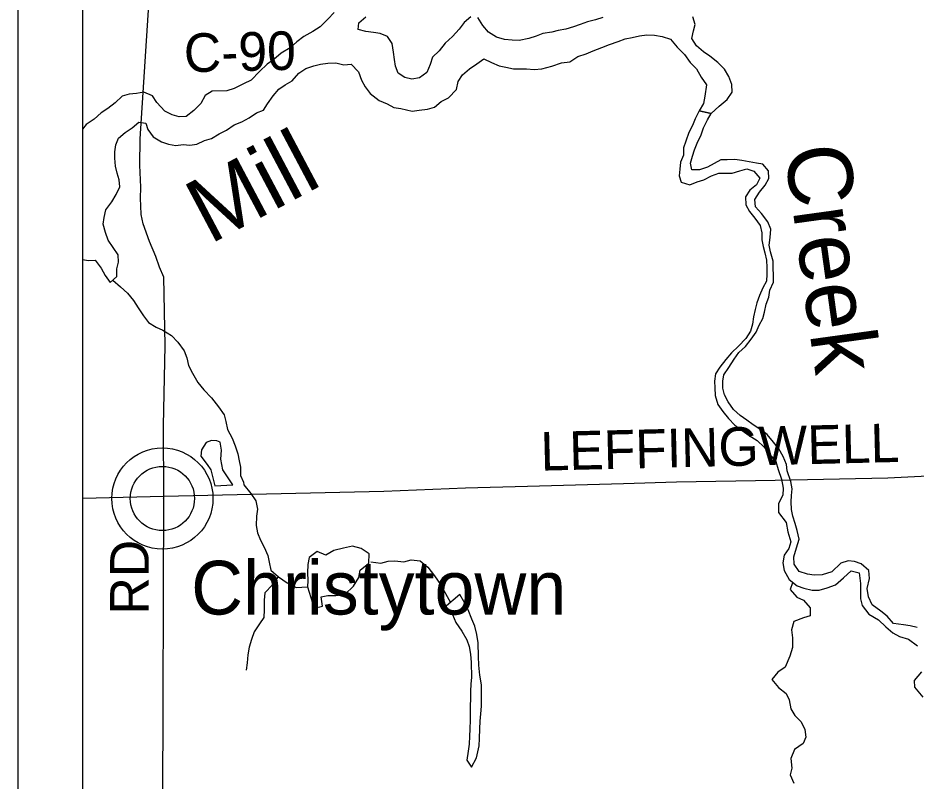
# Model space of a CAD drawing. Extents: x 0 to 34, y 0 to 22.
# Drawn here: x 2.895 to 4.215, y 15.405 to 16.527 of the extents above; entities that cross this region are included whole.
import ezdxf

# ---------------------------------------------------------------- set-up
doc = ezdxf.new("R2010")
doc.units = 0
for name, color, linetype in [('GM_X_Corporation', 7, 'Continuous'), ('GM_X_County_Road', 7, 'Continuous'), ('GM_X_County_Road_Text', 7, 'Continuous'), ('GM_X_Major_Lake', 7, 'Continuous'), ('GM_X_Minor_Lake', 7, 'Continuous'), ('GM_X_Minor_River', 7, 'Continuous'), ('GM_X_Minor_River_Text', 7, 'Continuous'), ('GM_X_Township_Road', 7, 'Continuous'), ('GM_X_Unincorporated', 7, 'Continuous'), ('GM_X_Unincorporated_Location', 7, 'Continuous'), ('GM_X_Unincorporated_Text', 7, 'Continuous'), ('SH_Data', 7, 'Continuous')]:
    doc.layers.add(name, color=color, linetype=linetype)

msp = doc.modelspace()

# ---------------------------------------------------------------- linework, layer by layer
at = {"layer": 'GM_X_Corporation'}
msp.add_lwpolyline([(2.9895, 20.1176), (2.9895, 14.989), (3.1061, 14.9902), (3.7218, 15.0051), (5.1362, 15.0301), (5.7825, 15.0418), (6.0746, 15.0468), (7.3134, 15.0684), (7.3375, 15.0689), (7.3129, 15.9614), (7.3097, 16.0633), (7.3049, 16.5704), (7.3046, 16.5913), (7.2998, 16.7507), (7.2943, 16.935), (7.2911, 17.0516), (7.2872, 17.1772), (7.283, 17.3071)], dxfattribs=at)
at = {"layer": 'GM_X_County_Road'}
msp.add_line((3.1063, 14.9896), (3.1089, 15.8232), dxfattribs=at)
for points in [[(3.1089, 15.8232), (3.1084, 15.9273), (3.111, 16.0453), (3.109, 16.1457), (3.1029, 16.1604), (3.0973, 16.1762), (3.088, 16.1981), (3.0786, 16.2241), (3.076, 16.2381), (3.0753, 16.2506), (3.0747, 16.2617), (3.0751, 16.278), (3.0739, 16.3103), (3.0741, 16.3491), (3.0868, 16.5462), (3.0859, 16.5875), (3.0837, 16.6669), (3.0819, 16.7328), (3.081, 16.7772), (3.0772, 16.8841), (3.0725, 17.0072), (3.0711, 17.0638), (3.0667, 17.2336), (3.0632, 17.3772)], [(5.1195, 15.8708), (4.6505, 15.8645), (4.2722, 15.8551), (4.1739, 15.8504), (4.0083, 15.847), (3.8632, 15.8442), (3.7853, 15.842), (3.644, 15.8378), (3.5529, 15.8354), (3.4325, 15.8307), (3.1089, 15.8232)]]:
    msp.add_lwpolyline(points, dxfattribs=at)
at = {"layer": 'GM_X_Major_Lake'}
for points in [[(3.3595, 16.5349), (3.3501, 16.525), (3.3388, 16.5139), (3.3282, 16.5073), (3.315, 16.4996), (3.3048, 16.4919), (3.295, 16.4831), (3.2817, 16.475), (3.2708, 16.4658), (3.2609, 16.4589), (3.2496, 16.4485), (3.2376, 16.4355), (3.2262, 16.4301), (3.2126, 16.4235), (3.202, 16.4196), (3.1803, 16.4195), (3.1701, 16.4129), (3.1637, 16.4011), (3.1531, 16.3911), (3.1418, 16.3819), (3.1315, 16.3818)], [(3.5604, 16.5286), (3.5506, 16.5201), (3.5435, 16.5106), (3.5337, 16.4998), (3.5231, 16.4899), (3.5141, 16.4788), (3.5043, 16.4692), (3.5006, 16.4585), (3.4961, 16.4467), (3.4851, 16.439), (3.4741, 16.437), (3.4634, 16.4396), (3.4539, 16.446), (3.45, 16.4562), (3.4484, 16.4657), (3.4468, 16.4767), (3.4448, 16.4892), (3.4382, 16.4998), (3.4275, 16.5039), (3.4176, 16.5057), (3.4062, 16.5072), (3.3951, 16.5101), (3.3958, 16.5196), (3.4064, 16.5285)], [(3.7548, 16.5275), (3.7441, 16.5243), (3.7324, 16.5212), (3.7214, 16.5173), (3.7115, 16.5138), (3.7005, 16.5103), (3.6891, 16.5087), (3.6796, 16.5063), (3.6667, 16.5039), (3.6569, 16.5004), (3.6459, 16.4969), (3.6318, 16.4938), (3.6212, 16.4941), (3.6101, 16.4951), (3.5983, 16.4988), (3.5865, 16.506), (3.5784, 16.5158), (3.5711, 16.5275)], [(3.914, 16.3867), (3.9259, 16.3973), (3.9376, 16.4073), (3.9448, 16.418), (3.9443, 16.429), (3.94, 16.4411), (3.9338, 16.4517), (3.9238, 16.4615), (3.9123, 16.4706), (3.9028, 16.4773), (3.8924, 16.486), (3.8859, 16.4966), (3.8881, 16.508), (3.8906, 16.5175), (3.8871, 16.5285)], [(3.0422, 16.1679), (3.0421, 16.1789), (3.0344, 16.1895), (3.027, 16.2004), (3.0231, 16.2114), (3.02, 16.2239), (3.0214, 16.2338), (3.024, 16.2449), (3.0326, 16.2564), (3.039, 16.2674), (3.0446, 16.2785), (3.0434, 16.2891), (3.0406, 16.299), (3.0379, 16.3092), (3.037, 16.3206), (3.0369, 16.3301), (3.0384, 16.3404), (3.0424, 16.3503), (3.0523, 16.3584), (3.0625, 16.3653), (3.0723, 16.3737), (3.0826, 16.3723), (3.0857, 16.3628), (3.0934, 16.3523), (3.1056, 16.3447), (3.1159, 16.3414), (3.1266, 16.3396), (3.1376, 16.3408), (3.1475, 16.3398), (3.1574, 16.3414), (3.1691, 16.3468), (3.179, 16.3499), (3.1903, 16.3568), (3.2013, 16.3622), (3.2127, 16.3696), (3.2237, 16.3742), (3.2346, 16.38), (3.2456, 16.3873), (3.2555, 16.3912), (3.2618, 16.4007), (3.2697, 16.4126), (3.278, 16.4221), (3.2878, 16.4287), (3.2977, 16.4345), (3.3078, 16.4456), (3.318, 16.4529), (3.3298, 16.4568), (3.3397, 16.4588), (3.3503, 16.4607), (3.3621, 16.4612), (3.3739, 16.4583), (3.3845, 16.4591), (3.3953, 16.4478), (3.4, 16.4357), (3.405, 16.4258), (3.4127, 16.416), (3.4257, 16.4055), (3.4375, 16.4006), (3.4475, 16.3954), (3.4578, 16.3939), (3.4742, 16.3899), (3.4844, 16.3915), (3.4969, 16.3931), (3.5072, 16.3959), (3.517, 16.4039), (3.528, 16.4093), (3.5397, 16.422), (3.5422, 16.4334), (3.5486, 16.4433), (3.5588, 16.4521), (3.5694, 16.4594), (3.5796, 16.4668), (3.591, 16.4615), (3.6021, 16.4567), (3.612, 16.4545), (3.6235, 16.4523), (3.6425, 16.4524), (3.6539, 16.4514), (3.6649, 16.4522), (3.6797, 16.4562), (3.6941, 16.4608), (3.7063, 16.4624), (3.718, 16.4701), (3.7305, 16.474), (3.7404, 16.4787), (3.7533, 16.4837), (3.7646, 16.488), (3.7771, 16.4923), (3.7877, 16.4965), (3.798, 16.4982), (3.8086, 16.5009), (3.8196, 16.5021), (3.8307, 16.5018), (3.8421, 16.4996), (3.8543, 16.4956), (3.8639, 16.4842), (3.8747, 16.4733), (3.8831, 16.4616), (3.8927, 16.4522), (3.8993, 16.4397), (3.9074, 16.4287)], [(3.9074, 16.4287), (3.9049, 16.412), (3.9027, 16.4013), (3.8965, 16.3906)], [(3.1315, 16.3818), (3.1213, 16.3844), (3.1106, 16.39), (3.0987, 16.4025), (3.0925, 16.4127), (3.0799, 16.4179), (3.0689, 16.4159), (3.0582, 16.4147), (3.0476, 16.4119), (3.0374, 16.4024), (3.0268, 16.3939), (3.017, 16.3874), (3.0068, 16.3782), (2.9951, 16.3705), (2.9895, 16.3633)], [(3.8965, 16.3906), (3.914, 16.3867)], [(2.9895, 16.1719), (2.9984, 16.1702), (3.0079, 16.1706), (3.0167, 16.1593), (3.0226, 16.1483), (3.0302, 16.1381), (3.0401, 16.1466), (3.04, 16.158), (3.0422, 16.1679)]]:
    msp.add_lwpolyline(points, dxfattribs=at)
at = {"layer": 'GM_X_Minor_Lake'}
for points in [[(3.2106, 15.8406), (3.1959, 15.8625), (3.193, 15.878), (3.194, 15.8914), (3.1919, 15.9031), (3.187, 15.9053), (3.179, 15.9056), (3.1714, 15.9025), (3.1647, 15.8918), (3.1633, 15.8826), (3.173, 15.8702), (3.178, 15.8627), (3.184, 15.8391)], [(3.184, 15.8391), (3.2106, 15.8406)], [(3.3302, 15.6591), (3.3423, 15.6623), (3.3405, 15.676), (3.3503, 15.6777), (3.3621, 15.6779), (3.3757, 15.6797), (3.388, 15.6913), (3.3957, 15.704), (3.3978, 15.715), (3.4104, 15.7255), (3.4113, 15.7388), (3.3994, 15.747), (3.3865, 15.7505), (3.3733, 15.7476), (3.3593, 15.7439), (3.3473, 15.7372), (3.3344, 15.7423), (3.3231, 15.7337), (3.3207, 15.7231), (3.3205, 15.7109), (3.3207, 15.6999), (3.3205, 15.6904)], [(3.3205, 15.6904), (3.3302, 15.6591)], [(3.5215, 15.6596), (3.5335, 15.65), (3.5386, 15.6379), (3.5472, 15.6252), (3.5546, 15.6128), (3.5582, 15.6026), (3.5603, 15.5916), (3.5613, 15.5791), (3.5617, 15.5578), (3.5607, 15.5475), (3.5602, 15.5373), (3.56, 15.5278), (3.5599, 15.5137), (3.5597, 15.5042), (3.5598, 15.4947), (3.559, 15.481), (3.5588, 15.4708), (3.5582, 15.459), (3.5569, 15.4487), (3.5549, 15.4358), (3.5615, 15.4252), (3.5688, 15.4391), (3.5727, 15.4566), (3.5732, 15.4676), (3.5737, 15.4817), (3.5743, 15.4931), (3.5752, 15.5038), (3.5761, 15.5148), (3.5763, 15.5269), (3.5765, 15.5364), (3.5763, 15.5463), (3.5741, 15.5607), (3.5724, 15.5755), (3.5717, 15.588), (3.5714, 15.6081), (3.5696, 15.6206), (3.5664, 15.6327), (3.562, 15.6429), (3.5568, 15.6565), (3.5517, 15.6663), (3.5447, 15.6794)], [(3.5447, 15.6794), (3.5215, 15.6596)]]:
    msp.add_lwpolyline(points, dxfattribs=at)
at = {"layer": 'GM_X_Minor_River'}
for points in [[(3.8965, 16.3906), (3.8907, 16.3788), (3.8866, 16.3689), (3.8814, 16.3586), (3.8769, 16.346), (3.8732, 16.3361), (3.8733, 16.325), (3.8688, 16.3151), (3.8682, 16.3045), (3.8671, 16.295), (3.8702, 16.2855), (3.8828, 16.2814), (3.8934, 16.2861), (3.9033, 16.2888), (3.9147, 16.2946), (3.9253, 16.2989), (3.9355, 16.2986), (3.9451, 16.2986), (3.9564, 16.3021), (3.9667, 16.3053), (3.977, 16.3015), (3.9858, 16.2914), (3.981, 16.2818), (3.9711, 16.2738), (3.9648, 16.2638), (3.9649, 16.2524), (3.9703, 16.2426), (3.9783, 16.2328), (3.9864, 16.2218), (3.9888, 16.2108), (3.9885, 16.2005), (3.9905, 16.191), (3.9932, 16.1816), (3.9956, 16.1706), (3.9961, 16.1603), (3.9962, 16.1504), (3.9955, 16.1402), (3.9899, 16.1302), (3.9851, 16.1188), (3.9813, 16.1081), (3.9788, 16.0982), (3.9766, 16.0875), (3.9748, 16.0765), (3.9722, 16.0666), (3.9651, 16.0559), (3.9545, 16.0444), (3.944, 16.0344), (3.9357, 16.0249), (3.927, 16.0134), (3.9206, 16.0039), (3.9192, 15.9928), (3.9193, 15.9833), (3.9202, 15.9719), (3.9237, 15.9586), (3.9314, 15.9481), (3.9395, 15.9382), (3.9491, 15.9284), (3.9598, 15.9202), (3.9701, 15.913), (3.9816, 15.9055), (3.992, 15.8961), (3.9993, 15.8859), (4.0093, 15.8746), (4.0128, 15.8628), (4.0174, 15.849)], [(3.8971, 16.3036), (3.8857, 16.3039), (3.8837, 16.3133), (3.8866, 16.3236), (3.8896, 16.3332), (3.8937, 16.3427), (3.8993, 16.3549), (3.903, 16.3656), (3.9086, 16.377), (3.914, 16.3867)], [(3.914, 16.3867), (3.8965, 16.3906)], [(4.0311, 15.8455), (4.0261, 15.861), (4.0249, 15.8705), (4.0198, 15.8823), (4.0137, 15.8936), (4.0056, 15.9034), (3.9967, 15.9144), (3.9872, 15.9215), (3.9761, 15.9287), (3.9665, 15.9358), (3.9566, 15.9422), (3.947, 15.9512), (3.9389, 15.9626), (3.9339, 15.9728), (3.9311, 15.9827), (3.9314, 15.9929), (3.9328, 16.0024), (3.94, 16.0131), (3.9478, 16.0254), (3.9546, 16.0349), (3.9648, 16.0441), (3.9731, 16.0548), (3.9802, 16.0651), (3.9847, 16.0754), (3.9899, 16.085), (3.9925, 16.0945), (3.9951, 16.1059), (3.9988, 16.1162), (4.0006, 16.1269), (4.0058, 16.1387), (4.0055, 16.1695), (4.0016, 16.1832), (3.9996, 16.193), (4.001, 16.2044), (4.0021, 16.2166), (3.9974, 16.2272), (3.9882, 16.2397), (3.9793, 16.2495), (3.9785, 16.2601), (3.9852, 16.2708), (3.9935, 16.2812), (3.9991, 16.2911), (3.9986, 16.3021), (3.9902, 16.3119), (3.9807, 16.3137), (3.9593, 16.3174), (3.9487, 16.3188), (3.9377, 16.3183), (3.9281, 16.3186), (3.9183, 16.3129), (3.9085, 16.3075), (3.8971, 16.3036)], [(3.0341, 16.1415), (3.0455, 16.1318), (3.0559, 16.1224), (3.0643, 16.1114), (3.0713, 16.1008), (3.0794, 16.0891), (3.0867, 16.0793), (3.0978, 16.0721), (3.1077, 16.0677), (3.1203, 16.0602), (3.1295, 16.0504), (3.1388, 16.0375), (3.1427, 16.0273), (3.1454, 16.0159), (3.1512, 16.0045), (3.159, 15.9909), (3.1678, 15.9803), (3.1793, 15.9683), (3.1893, 15.955), (3.1978, 15.9433), (3.2005, 15.9335), (3.2029, 15.9217), (3.2095, 15.9092), (3.2138, 15.8978), (3.2177, 15.8861), (3.2201, 15.8759), (3.2217, 15.8664), (3.2218, 15.8542), (3.2261, 15.8444), (3.2268, 15.8406)], [(3.2268, 15.8406), (3.2373, 15.8279), (3.2443, 15.817), (3.2468, 15.8045), (3.2455, 15.7942), (3.245, 15.7809), (3.2467, 15.7699), (3.2515, 15.759), (3.2566, 15.7488), (3.2621, 15.7368), (3.2642, 15.7266), (3.2667, 15.7152), (3.2778, 15.7052), (3.2905, 15.6963), (3.3039, 15.6897), (3.3205, 15.6904)], [(4.0174, 15.849), (4.0199, 15.8358), (4.0194, 15.8255), (4.0131, 15.8132), (4.013, 15.7996), (4.0243, 15.785), (4.0268, 15.7713), (4.0312, 15.7566), (4.0284, 15.7471), (4.0217, 15.7371), (4.0197, 15.726), (4.0214, 15.7143), (4.0288, 15.7015), (4.0408, 15.6918), (4.0503, 15.6886), (4.0629, 15.6858), (4.0731, 15.6856), (4.0848, 15.6889), (4.0968, 15.6933), (4.1088, 15.7037), (4.1199, 15.7142), (4.1317, 15.711), (4.1339, 15.6955), (4.1337, 15.6848), (4.1336, 15.6731), (4.136, 15.6629), (4.1461, 15.6505), (4.1603, 15.642), (4.1711, 15.6316), (4.1815, 15.6231), (4.1911, 15.6176), (4.2044, 15.6136), (4.2178, 15.6036)], [(4.217, 15.6306), (4.207, 15.6334), (4.1972, 15.6344), (4.1824, 15.6368), (4.1731, 15.6476), (4.1635, 15.6546), (4.1508, 15.6639), (4.1453, 15.6756), (4.1435, 15.6881), (4.147, 15.7026), (4.1461, 15.7143), (4.1349, 15.7244), (4.125, 15.7276), (4.1155, 15.7289), (4.1049, 15.7253), (4.0915, 15.7125), (4.0772, 15.7081), (4.0655, 15.7079), (4.0556, 15.7092), (4.0434, 15.7132), (4.0364, 15.724), (4.0358, 15.7347), (4.0397, 15.748), (4.0437, 15.7606), (4.0404, 15.7735), (4.0376, 15.7837), (4.0343, 15.7943), (4.0323, 15.8041), (4.032, 15.8155), (4.0322, 15.825), (4.0332, 15.8345), (4.0311, 15.8455)], [(3.4138, 15.7275), (3.4283, 15.7251), (3.4392, 15.7283), (3.449, 15.7285), (3.4619, 15.7273), (3.4729, 15.7301), (3.4862, 15.7285), (3.4973, 15.7196), (3.507, 15.7068), (3.516, 15.6937), (3.5305, 15.6673)], [(3.2774, 15.7056), (3.269, 15.6932), (3.2578, 15.6816), (3.2565, 15.671), (3.2568, 15.6569), (3.2562, 15.6455), (3.2496, 15.6359), (3.2418, 15.6243), (3.2379, 15.6132), (3.2347, 15.6018), (3.2326, 15.5907), (3.2317, 15.5789), (3.2304, 15.5679)], [(4.0342, 15.6971), (4.0339, 15.6966), (4.0303, 15.6867), (4.0403, 15.6755), (4.0499, 15.6707), (4.0596, 15.6595), (4.0598, 15.6477), (4.05, 15.6449), (4.0357, 15.6397), (4.0321, 15.6271), (4.0338, 15.6157), (4.0337, 15.6013), (4.0298, 15.5887), (4.0229, 15.5726), (4.0121, 15.5648), (4.0035, 15.554), (4.0132, 15.5424), (4.0244, 15.5339), (4.0287, 15.5241), (4.0312, 15.5112), (4.0371, 15.5015), (4.0467, 15.4921), (4.0519, 15.4805), (4.0536, 15.4695), (4.0492, 15.4599), (4.0365, 15.4513), (4.0315, 15.4379), (4.0329, 15.4239), (4.0304, 15.4143), (4.0355, 15.4019)], [(4.2235, 15.5654), (4.2127, 15.5526), (4.2133, 15.5431), (4.2253, 15.5282)]]:
    msp.add_lwpolyline(points, dxfattribs=at)
at = {"layer": 'GM_X_Township_Road'}
msp.add_line((3.1089, 15.8232), (2.9895, 15.8206), dxfattribs=at)
at = {"layer": 'GM_X_Unincorporated'}
for radius in [0.0744, 0.0472]:
    msp.add_circle((3.107, 15.8204), radius, dxfattribs=at)
at = {"layer": 'GM_X_Unincorporated_Location'}
msp.add_line((3.107, 15.8204), (3.107, 15.8204), dxfattribs=at)
at = {"layer": 'SH_Data'}
msp.add_line((2.8945, 20.8873), (2.8945, 13.8873), dxfattribs=at)

# ---------------------------------------------------------------- texts
at = {"layer": 'GM_X_County_Road_Text'}
for s, height, rotation, p in [('C-90', 0.05682, 1.3726, (3.1392, 16.447)), ('LEFFINGWELL', 0.056818, 1.397, (3.6638, 15.8613)), ('RD', 0.05682, 90, (3.0869, 15.6498))]:
    msp.add_text(s, height=height, rotation=rotation, dxfattribs=at).set_placement(p)
at = {"layer": 'GM_X_Minor_River_Text'}
for s, height, rotation, p in [('Mill', 0.09473, 27.924, (3.1767, 16.1935)), ('Creek', 0.09474, 277.8683, (4.0215, 16.3351))]:
    msp.add_text(s, height=height, rotation=rotation, dxfattribs=at).set_placement(p)
at = {"layer": 'GM_X_Unincorporated_Text'}
msp.add_text('Christytown', height=0.078977, rotation=0, dxfattribs=at).set_placement((3.1493, 15.6498))

doc.saveas('drawing.dxf')
